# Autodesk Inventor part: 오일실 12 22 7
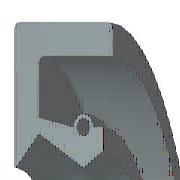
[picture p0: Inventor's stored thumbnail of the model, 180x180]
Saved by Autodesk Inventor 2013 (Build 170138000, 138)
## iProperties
Created: 2012-02
Part Number: 오일실 12 22 7
Material: 고무
Description: 오일-실
Document SubType Name: Modeling
Standard: KS B 2804
Designer: mduedu
Standards Organization: KS
Language: ko-KR
Size Designation: D - 12 22 7
Categories: <MemberInstance><Categories><Category DisplayName="샤프트 부품" InternalName="7f7aeb1f-a693-4053-b835-cee3144e0d98" Mnemonic="SHFT"><Category DisplayName="실링" Intern
Density: 0.55 g/cm^3
Mass: 0.74151 g
Surface Area: 18.4996 cm^2
Volume: 1.3482 cm^3
IsCustomPart: 1
Author: mduedu
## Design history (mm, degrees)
revolve "본체" stored, may be unused: angle "d17" = 90 deg
revolve "스프링1" stored, may be unused: angle "d18" = 90 deg
body "Solid1"
sketch "스케치1"
  geometry: L1 (0, 11)-(7, 11); L2 (7, 9.25)-(1.75, 9.25); L3 (1.75, 7.75)-(4.9, 6); L4 (4.9, 6)-(0, 6); L5 (0, 0)-(9.586, 0) reference; L6 (4.9, 6)-(6.3, 6.875); L7 (0, 18)-(0, -3) reference; L8 (-1.941, 0)-(11.507, 0) reference; L9 (4.2, 8.1)-(1.75, 8.59); L10 (1.75, 8.59)-(1.75, 9.25); L11 (0, 11)-(0, 6.088); L12 (4.9, 6)-(0, 6); L13 (1.75, 7.75)-(0.152, 6.028); L14 (7, 11)-(7, 9.25); L15 (5.6, 8.1)-(6.3, 8.1); L16 (6.3, 8.1)-(6.3, 6.875); C1 r 0.455 at (4.9, 8.1); A1 r 0.7 centre (4.9, 8.1) between (5.6, 8.1) and (4.2, 8.1); A2 r 0.088 centre (0.088, 6.088) between (0, 6.088) and (0.152, 6.028); 1 further point
  constraints: 28 end point, 5 horizontal alignment, 5 point on line, 4 point on circle, 4 vertical alignment, 3 centre point, 3 tangent, 2 collinear, 2 horizontal, 2 perpendicular, 1 coincident, 1 parallel
  dimensions: "d0" = 22 diameter of L1 L5 (= SD2); "d1" = 1.75 distance of L1.end L2.start (= SD); "d2" = 0.91 diameter of C1 (= SPDI); "d3" = 1.4 diameter of A1 (= SPDA); "d4" = 12 diameter of L3.end L5 (= NND); "d5" = 15.5 diameter of L3.start L5 (= TKDM); "d7" = 17.18 diameter of L9.end L5 (= TKDM + 0.24 x SWDT); "d8" = 1.75 distance between parallel lines of L11 L10 (= SD); "d9" = 4.9 distance from line of L11 C1.centre (= SPDST); "d10" = 16.2 diameter of C1.centre L5 (= HLDM); "d11" = 0.0875 radius of A2 (= 0.25 x LAB); "d12" = 6.3 distance between parallel lines of L11 L16 (= SDI); "d13" = 13.75 diameter of L6.end L5 (= ABDM); "d14" = 7 distance from line of L11 L1.end (= SWDT)
fillet "모깎기1" dims "d6" = 0.3 (= RR)
other parameters: "SD2" = 22 [user parameter; used in 1 equation term], "SWDT" = 7 [user parameter; used in 2 equation terms], "RR" = 0.3 [user parameter; used in 1 equation term], "SD" = 1.75 [user parameter; used in 2 equation terms], "NND" = 12 [user parameter; used in 1 equation term], "SPDA" = 1.4 [user parameter; used in 1 equation term], "SPDI" = 0.91 [user parameter; used in 1 equation term], "TKDM" = 15.5 [user parameter; used in 2 equation terms], "HLDM" = 16.2 [user parameter; used in 1 equation term], "ABDM" = 13.75 [user parameter; used in 1 equation term], "SDI" = 6.3 [user parameter; used in 1 equation term], "SPDST" = 4.9 [user parameter; used in 1 equation term], "LAB" = 0.35 [user parameter; used in 1 equation term], "d15" = 0, "d16" = 0, "d19" = 0
